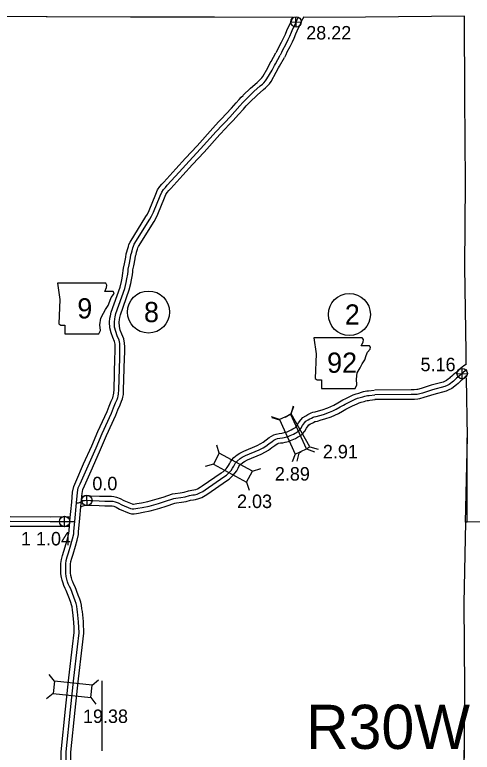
# Model space of a CAD drawing. Extents: x 31699 to 244310, y -8841 to 11474.
# Drawn here: x 102114 to 103072, y 4850 to 6393 of the extents above; entities that cross this region are included whole.
import ezdxf

# ---------------------------------------------------------------- set-up
doc = ezdxf.new("R2010")
doc.units = 0
for name, color, linetype in [('B_Logo', 7, 'Continuous'), ('Default', 7, 'Continuous'), ('G-ANNO-TEXT', 7, 'Continuous'), ('Level 21', 7, 'Continuous'), ('R_Border', 7, 'Continuous'), ('R_Border Notes', 7, 'Continuous'), ('R_Logo', 7, 'Continuous'), ('R_XS_EARTHWORK_STAGE1', 7, 'Continuous'), ('R_XS_EARTHWORK_STAGE2', 7, 'Continuous'), ('S_WALL', 7, 'Continuous'), ('S_WALL_ANNOT', 7, 'Continuous')]:
    doc.layers.add(name, color=color, linetype=linetype)

msp = doc.modelspace()

# ---------------------------------------------------------------- linework, layer by layer
at = {"layer": 'B_Logo'}
for points in [[(102707.1, 6388.4), (102704.5, 6382.7), (102701.3, 6375.7), (102698.4, 6369.4), (102695.1, 6363.2), (102692.1, 6356), (102689, 6347.8), (102685.5, 6340.5), (102680.4, 6330.5), (102674.5, 6319), (102672.2, 6313.9), (102669.4, 6308.7)], [(102598.9, 6217.5), (102614.3, 6232.3), (102627.6, 6244.3), (102632.2, 6248), (102635.5, 6251), (102639, 6254.9), (102641.7, 6259), (102652.3, 6277.6), (102657.5, 6287.3), (102659.5, 6290.5), (102669.4, 6308.7)], [(102244.7, 5393.2), (102246.7, 5402.9), (102250.6, 5411.5), (102267, 5449.3), (102284.1, 5487.1), (102296.5, 5516.9), (102315.9, 5559.2), (102320.5, 5570.3), (102324.9, 5580.8), (102328, 5587.9), (102329.5, 5592.3), (102330.3, 5595.3), (102331.2, 5599.8), (102331.6, 5608.6), (102333.5, 5674.7), (102334, 5686.5), (102334, 5698.2), (102333.7, 5705.2), (102332.3, 5712.2), (102328.4, 5721.4), (102325.2, 5730.4), (102322.7, 5739.5), (102322.3, 5749.9), (102322.9, 5757), (102323.7, 5761.4), (102325.3, 5767.9), (102343.8, 5820.2), (102347.2, 5832.7), (102348.4, 5840.3), (102350.1, 5850.7), (102350.8, 5856.6), (102351.3, 5860.9), (102353.4, 5869.7), (102355.8, 5884.3), (102357, 5890.7), (102357.9, 5894.4), (102359.3, 5899), (102361.2, 5905.5), (102362.2, 5908.9), (102364, 5912.8), (102396.8, 5965.7), (102400.1, 5971.4), (102404.3, 5979.8), (102418.1, 6014.1), (102421.5, 6022), (102425.2, 6027.6), (102429, 6031.9), (102433.1, 6036.6), (102458, 6064.1), (102478.6, 6086.5), (102502.6, 6112.3), (102535.7, 6149.1), (102547.9, 6162.2), (102554, 6168.8), (102563.7, 6178.8), (102574.8, 6191.1), (102584.9, 6202.3), (102591, 6209.4), (102595.2, 6213.7), (102598.9, 6217.5)], [(103060.3, 5650.4), (103060.1, 5650.3), (103053.2, 5645.2), (103050.4, 5642.8), (103045.6, 5638.1), (103041.5, 5634.9), (103038.7, 5632.5), (103035.2, 5629.2), (103032.1, 5626.7)], [(103032.1, 5626.7), (103023.6, 5619.7), (103021.8, 5618.9), (103019.4, 5617.7), (103013.9, 5615.2), (102988.3, 5608.4), (102967.6, 5601.5), (102959.2, 5599.3), (102956.5, 5598.8), (102950.2, 5598.4), (102943.6, 5598.3), (102867.3, 5597.8)], [(102512, 5399), (102551.3, 5426.1), (102556.8, 5429.4), (102560.8, 5433.1), (102564.1, 5436.7), (102566.5, 5439.7), (102569.9, 5444.4), (102572.3, 5448.8), (102574.3, 5452.8), (102576.2, 5455.7), (102579.5, 5459.3), (102585.4, 5464.5), (102589.6, 5467.2), (102597.1, 5470.8), (102625.2, 5482.9), (102633.6, 5487.1), (102639.2, 5490.5), (102646, 5495.6), (102652.4, 5500.3), (102656, 5502.7), (102660.3, 5505.1), (102663.5, 5506.1), (102668.5, 5507.2), (102674, 5507.6), (102677.8, 5508.3), (102683.5, 5509.9), (102687.4, 5511.3), (102690.6, 5512.6), (102697.2, 5515.6), (102700.9, 5517.8), (102703.4, 5519.1), (102707.4, 5521.6), (102709.3, 5523.2), (102712.7, 5527.2), (102716.1, 5533.6), (102720.2, 5539.3), (102723.2, 5542.5), (102728, 5545.7), (102731.7, 5547.7), (102734.8, 5549.1), (102738.3, 5550.9), (102740.4, 5551.7), (102745, 5552.5), (102752.3, 5554.9), (102760.1, 5556.9), (102772.6, 5561.5), (102779.8, 5564.5), (102786.7, 5567.7), (102795.1, 5572.5), (102801.8, 5576.5), (102805.4, 5578.4), (102811.2, 5581.3), (102816.9, 5584.1), (102826.7, 5588.5), (102831.6, 5590.7), (102836.6, 5592), (102842.4, 5593.6), (102846.5, 5594.8), (102849.8, 5595.5), (102852.6, 5596.1), (102855.5, 5596.6), (102867.3, 5597.8)], [(102221.2, 4806.1), (102221, 4850.6), (102230.1, 4938.6), (102237.1, 5004.6), (102244.8, 5070.1), (102248.2, 5099.9), (102248.2, 5102.9), (102248, 5108), (102247.9, 5111), (102247.3, 5122.9), (102245.2, 5143.4), (102244.4, 5148.9), (102243.5, 5155.8), (102242.2, 5161.1), (102240.4, 5166.6), (102237.3, 5174.7), (102230.8, 5192), (102228.4, 5196.9), (102225.8, 5202.6), (102224.3, 5206.4), (102222.8, 5212.4), (102221.5, 5217.7), (102220.4, 5224.3), (102220.3, 5229.9), (102220.3, 5237.4), (102220.4, 5244.2), (102221.3, 5251.2), (102223.3, 5258.6), (102226.2, 5267.5), (102231, 5284), (102234.6, 5296.4), (102237.1, 5307.1), (102237.5, 5312.5), (102239.2, 5332.9), (102242.8, 5372.1), (102244.7, 5393.2)], [(102242.8, 5372.1), (102247.4, 5372.1), (102249.2, 5372.8), (102250.5, 5373.5), (102252.7, 5374.6), (102255.1, 5375.6), (102256.4, 5376.1), (102260, 5376.8), (102263.1, 5377.1), (102272.1, 5376.7), (102290.6, 5376), (102302.3, 5375.5), (102311.8, 5375.6), (102315.4, 5375.6), (102319.3, 5375.2), (102323.8, 5374.2), (102330.4, 5371.6), (102337.6, 5367.6), (102356.2, 5359.9), (102359.7, 5359.1), (102363.2, 5359), (102367.1, 5359.6), (102371.3, 5360.3), (102380.7, 5362), (102394.8, 5364.9), (102404.9, 5367.6), (102414.4, 5370.4), (102427.4, 5374.5), (102446.5, 5380.9), (102450.7, 5381.5), (102461.5, 5383.1), (102470.5, 5384.6), (102479.6, 5387.1), (102486.3, 5388.3), (102490.3, 5388.8), (102495.8, 5390.2), (102500.9, 5392.4), (102507.3, 5395.7), (102512, 5399)], [(102104.1, 5333.1), (102187.9, 5332.8), (102239.2, 5332.9)]]:
    msp.add_lwpolyline(points, dxfattribs=at)
at = {"layer": 'Default'}
msp.add_line((102296.2, 4999.1), (102296.2, 4852.8), dxfattribs=at)
at = {"layer": 'G-ANNO-TEXT'}
for points in [[(102202.8, 5831.3), (102207.9, 5797.4), (102205.6, 5746.1), (102210.2, 5743.3), (102218.6, 5743.3), (102218.6, 5725.3), (102289.7, 5725.3), (102293.1, 5732.6), (102291.9, 5744.4), (102293.6, 5758), (102299.8, 5768.7), (102303.8, 5776.6), (102309.4, 5785), (102312.8, 5794), (102315.6, 5801.4), (102320.7, 5807.6), (102321.8, 5811.5), (102319.6, 5814.4), (102302.1, 5814.4), (102306, 5822.2), (102306.6, 5827.3), (102304.3, 5831.2)], [(102739.8, 5717.2), (102744.9, 5683.4), (102742.7, 5632.1), (102747.2, 5629.3), (102755.6, 5629.3), (102755.6, 5611.2), (102826.7, 5611.2), (102830.1, 5618.5), (102828.9, 5630.4), (102830.6, 5643.9), (102836.8, 5654.6), (102840.8, 5662.5), (102846.4, 5671), (102849.8, 5680), (102852.6, 5687.3), (102857.7, 5693.6), (102858.8, 5697.5), (102856.6, 5700.3), (102839.1, 5700.3), (102843, 5708.2), (102843.6, 5713.3), (102841.3, 5717.2)]]:
    msp.add_lwpolyline(points, close=True, dxfattribs=at)
at = {"layer": 'Level 21'}
for p, q in [((102691.7, 6378), (102713.4, 6378.5)), ((102702.8, 6367.4), (102702.3, 6389.1)), ((103050.8, 5631.4), (103050.3, 5653.1)), ((103039.7, 5642), (103061.4, 5642.5)), ((102264.9, 5366.2), (102264.4, 5387.9)), ((102253.8, 5376.8), (102275.5, 5377.3)), ((102218.1, 5321.9), (102217.6, 5343.6)), ((102207, 5332.5), (102228.7, 5333))]:
    msp.add_line(p, q, dxfattribs=at)
for centre in [(102702.6, 6378.2), (103050.5, 5642.2), (102264.6, 5377), (102217.9, 5332.8)]:
    msp.add_circle(centre, 10.9, dxfattribs=at)
at = {"layer": 'R_Border Notes'}
for centre in [(102393.7, 5771.1), (102814.3, 5766)]:
    msp.add_circle(centre, 44, dxfattribs=at)
at = {"layer": 'R_Logo'}
for points in [[(102696.2, 6387.4), (102531.9, 6387.9), (102358.4, 6388.1), (102355.8, 6388.5), (102181.6, 6388.9), (102179.6, 6388.9), (102005.1, 6390.4), (102003.4, 6390.4), (101829.9, 6391.6), (101826.9, 6391.9), (101654.1, 6392.9), (101649.9, 6393.1), (101606.2, 6393.3)], [(103059.1, 5662.1), (103058.7, 5687.5), (103056.2, 5864.8), (103057.3, 6042.5), (103056.4, 6220.8), (103055.4, 6390), (102847.8, 6388.1)], [(102847.8, 6388.1), (102719, 6387.8)], [(103057.5, 5331.4), (103061.8, 5510.2), (103059.6, 5632.5)], [(103061, 5331.5), (103061, 5507.5)], [(103766.5, 5336.1), (103736.6, 5336.3), (103686.7, 5336.6), (103590, 5337.3), (103413.2, 5334.7), (103411.6, 5334.8), (103233, 5334.1), (103230.4, 5334.1), (103061, 5331.5), (103057.5, 5331.4), (103053.7, 5162.1), (103055.2, 4984.7), (103054.3, 4811.7)], [(103167.5, 5333.1), (103061, 5331.5), (103057.5, 5331.4), (103053.7, 5162.1), (103055.2, 4984.7), (103054.2, 4787.8)]]:
    msp.add_lwpolyline(points, dxfattribs=at)
at = {"layer": 'R_XS_EARTHWORK_STAGE1'}
for p, q in [((102692, 5556.8), (102698.2, 5573.3)), ((102692.5, 5557.9), (102697.1, 5574.8)), ((102692.5, 5557.9), (102680, 5550.7)), ((102731.7, 5489.1), (102692.5, 5557.9)), ((102668, 5545.9), (102651.5, 5552.1)), ((102668.7, 5545), (102652.6, 5549.4)), ((102542, 5476), (102536.9, 5492.8)), ((102724.8, 5484.7), (102741.2, 5478.5)), ((102725.3, 5485.4), (102731.7, 5489.1)), ((102731.7, 5489.1), (102748.7, 5484.4)), ((102700.7, 5473.8), (102694.5, 5457.3)), ((102708.8, 5476), (102704.2, 5459)), ((102708.5, 5476.5), (102708.8, 5476)), ((102708.8, 5476), (102713.2, 5478.5)), ((102529.5, 5452.7), (102512.6, 5447.7)), ((102611.7, 5438.4), (102628.6, 5443.5)), ((102599.2, 5415.2), (102604.3, 5398.3)), ((102196.7, 4998.8), (102185.6, 5012.5)), ((102275.4, 4990.4), (102289.1, 5001.5)), ((102193.9, 4972.6), (102180.2, 4961.5)), ((102272.6, 4964.2), (102283.7, 4950.5))]:
    msp.add_line(p, q, dxfattribs=at)
for points in [[(102668, 5545.9), (102700.7, 5473.8), (102724.8, 5484.7), (102692, 5556.8)], [(102529.5, 5452.7), (102599.2, 5415.2), (102611.7, 5438.4), (102542, 5476)], [(102275.4, 4990.4), (102196.7, 4998.8), (102193.9, 4972.6), (102272.6, 4964.2)]]:
    msp.add_lwpolyline(points, close=True, dxfattribs=at)
at = {"layer": 'R_XS_EARTHWORK_STAGE2'}
for points in [[(102696.2, 6388.5), (102695.5, 6386.9), (102692.2, 6379.9), (102689.5, 6373.8), (102686, 6367.5), (102682.8, 6359.7), (102679.8, 6351.7), (102676.5, 6344.9), (102671.5, 6335.1), (102665.5, 6323.3), (102663.3, 6318.4), (102660.6, 6313.4)], [(102719, 6388.8), (102716.1, 6384), (102713.6, 6378.5), (102710.4, 6371.5), (102707.4, 6365), (102704.1, 6358.9), (102701.4, 6352.3), (102698.2, 6343.8), (102694.4, 6336), (102689.3, 6326), (102683.5, 6314.6), (102681.2, 6309.5), (102678.2, 6304)], [(102592, 6224.8), (102607.5, 6239.7), (102621.1, 6251.8), (102625.6, 6255.6), (102628.4, 6258.1), (102631.1, 6261.1), (102633.2, 6264.2), (102643.5, 6282.4), (102648.8, 6292.3), (102650.8, 6295.5), (102660.6, 6313.5)], [(102605.8, 6210.3), (102621.1, 6225), (102634.2, 6236.7), (102638.7, 6240.4), (102642.5, 6243.9), (102646.9, 6248.7), (102650.3, 6253.7), (102661, 6272.8), (102666.1, 6282.2), (102668.1, 6285.4), (102678.2, 6303.9)], [(102234.7, 5394.4), (102237.1, 5406), (102241.4, 5415.6), (102257.8, 5453.3), (102274.9, 5491.1), (102287.4, 5520.9), (102306.8, 5563.2), (102311.3, 5574.1), (102315.7, 5584.7), (102318.7, 5591.5), (102319.9, 5595.2), (102320.6, 5597.6), (102321.2, 5601), (102321.6, 5609), (102323.5, 5675.1), (102324, 5686.7), (102324, 5698), (102323.8, 5704), (102322.7, 5709.2), (102319, 5717.8), (102315.6, 5727.4), (102312.8, 5738), (102312.2, 5750.2), (102313, 5758.4), (102314, 5763.5), (102315.7, 5770.7), (102334.2, 5823.2), (102337.4, 5834.9), (102338.6, 5841.9), (102340.1, 5852.1), (102340.9, 5857.8), (102341.4, 5862.6), (102343.5, 5871.7), (102345.9, 5886), (102347.2, 5892.8), (102348.3, 5897), (102349.7, 5901.8), (102351.6, 5908.3), (102352.8, 5912.5), (102355.3, 5917.6), (102388.2, 5970.8), (102391.3, 5976.1), (102395.2, 5983.9), (102408.9, 6017.9), (102412.6, 6026.7), (102417.2, 6033.8), (102421.6, 6038.5), (102425.6, 6043.2), (102450.7, 6070.8), (102471.2, 6093.3), (102495.3, 6119.1), (102528.3, 6155.8), (102540.5, 6169), (102546.7, 6175.7), (102556.4, 6185.6), (102567.4, 6197.8), (102577.4, 6208.9), (102583.6, 6216.1), (102588, 6220.6), (102591.7, 6224.5)], [(102254.5, 5391.2), (102256.2, 5399.8), (102259.7, 5407.5), (102276.1, 5445.2), (102293.2, 5483.1), (102305.7, 5512.9), (102325.1, 5555.2), (102329.7, 5566.4), (102334.1, 5576.9), (102337.3, 5584.3), (102339, 5589.3), (102340.1, 5593.1), (102341.1, 5598.7), (102341.6, 5608.2), (102343.5, 5674.3), (102344, 5686.3), (102344, 5698.4), (102343.7, 5706.3), (102341.9, 5715.2), (102337.7, 5725.1), (102334.7, 5733.4), (102332.7, 5741), (102332.3, 5749.7), (102332.9, 5755.6), (102333.5, 5759.4), (102334.9, 5765.1), (102353.4, 5817.3), (102356.9, 5830.6), (102358.3, 5838.7), (102360, 5849.3), (102360.7, 5855.4), (102361.1, 5859.2), (102363.2, 5867.8), (102365.6, 5882.5), (102366.8, 5888.5), (102367.6, 5891.8), (102368.9, 5896.2), (102370.8, 5902.7), (102371.5, 5905.3), (102372.8, 5908), (102405.4, 5960.6), (102408.9, 5966.6), (102413.4, 5975.7), (102427.4, 6010.3), (102430.3, 6017.3), (102433.1, 6021.5), (102436.5, 6025.2), (102440.6, 6029.9), (102465.4, 6057.3), (102485.9, 6079.7), (102510, 6105.6), (102543.1, 6142.3), (102555.2, 6155.4), (102561.2, 6161.9), (102571, 6171.9), (102582.3, 6184.4), (102592.4, 6195.7), (102598.4, 6202.6), (102602.4, 6206.8), (102606.1, 6210.6)], [(103059.3, 5662.1), (103054.2, 5658.4), (103047, 5653), (103043.6, 5650.2), (103039, 5645.6), (103035.2, 5642.7), (103032, 5640), (103028.6, 5636.7), (103025.7, 5634.4)], [(103025.8, 5634.4), (103018.2, 5628.2), (103017.5, 5627.9), (103015.2, 5626.7), (103010.5, 5624.6), (102985.4, 5618), (102964.7, 5611.1), (102956.9, 5609), (102955.3, 5608.7), (102949.8, 5608.4), (102943.5, 5608.3), (102867.3, 5607.8)], [(103059.5, 5637.4), (103059.4, 5637.3), (103057.1, 5635.4), (103052.1, 5630.5), (103047.8, 5627.2), (103045.4, 5625.1), (103041.8, 5621.7), (103038.5, 5619)], [(103038.4, 5618.9), (103029, 5611.2), (103026.2, 5609.9), (103023.7, 5608.7), (103017.3, 5605.7), (102991.1, 5598.8), (102970.4, 5592), (102961.4, 5589.5), (102957.7, 5588.8), (102950.6, 5588.4), (102943.8, 5588.3), (102867.4, 5587.8)], [(102506.3, 5407.3), (102545.9, 5434.6), (102550.8, 5437.5), (102553.7, 5440.1), (102556.5, 5443.2), (102558.6, 5445.8), (102561.4, 5449.7), (102563.5, 5453.5), (102565.6, 5457.7), (102568.2, 5461.7), (102572.5, 5466.5), (102579.4, 5472.5), (102584.7, 5476), (102593, 5479.9), (102620.9, 5491.9), (102628.7, 5495.9), (102633.6, 5498.8), (102640, 5503.6), (102646.7, 5508.6), (102650.9, 5511.3), (102656.2, 5514.2), (102660.8, 5515.8), (102667.1, 5517.1), (102672.7, 5517.5), (102675.5, 5518.1), (102680.5, 5519.4), (102683.8, 5520.6), (102686.5, 5521.8), (102692.6, 5524.6), (102696.1, 5526.5), (102698.5, 5527.8), (102701.5, 5529.7), (102702.2, 5530.3), (102704.3, 5532.8), (102707.6, 5538.9), (102712.5, 5545.6), (102716.6, 5550.2), (102722.9, 5554.2), (102727.1, 5556.6), (102730.4, 5558.2), (102734.3, 5560.1), (102737.7, 5561.3), (102742.6, 5562.3), (102749.5, 5564.5), (102757.1, 5566.4), (102768.9, 5570.8), (102775.8, 5573.6), (102782.1, 5576.5), (102790, 5581.2), (102796.9, 5585.2), (102800.9, 5587.3), (102806.8, 5590.2), (102812.7, 5593.1), (102822.6, 5597.6), (102828.2, 5600.1), (102834, 5601.6), (102839.6, 5603.2), (102844, 5604.5), (102847.7, 5605.3), (102850.6, 5605.9), (102854.1, 5606.5), (102866.3, 5607.7)], [(102517.6, 5390.8), (102556.7, 5417.7), (102562.9, 5421.4), (102567.8, 5426), (102571.7, 5430.1), (102574.5, 5433.6), (102578.4, 5439), (102581.2, 5444.2), (102583.1, 5447.8), (102584.1, 5449.6), (102586.5, 5452.2), (102591.5, 5456.5), (102594.5, 5458.4), (102601.3, 5461.7), (102629.4, 5473.8), (102638.5, 5478.4), (102644.8, 5482.2), (102651.9, 5487.6), (102658, 5492.1), (102661.2, 5494.1), (102664.4, 5495.9), (102666.1, 5496.5), (102669.9, 5497.3), (102675.3, 5497.7), (102680.1, 5498.6), (102686.5, 5500.4), (102691, 5502), (102694.6, 5503.5), (102701.7, 5506.7), (102705.7, 5509), (102708.4, 5510.4), (102713.3, 5513.5), (102716.4, 5516.1), (102721, 5521.6), (102724.6, 5528.3), (102728, 5532.9), (102729.7, 5534.8), (102733.2, 5537.1), (102736.2, 5538.8), (102739.1, 5540.1), (102742.3, 5541.7), (102743.1, 5542), (102747.5, 5542.8), (102755.1, 5545.3), (102763.1, 5547.3), (102776.2, 5552.1), (102783.8, 5555.3), (102791.4, 5558.8), (102800.1, 5563.9), (102806.6, 5567.7), (102810, 5569.5), (102815.6, 5572.3), (102821.2, 5575), (102830.9, 5579.3), (102834.9, 5581.2), (102839.2, 5582.3), (102845.2, 5584), (102849, 5585.1), (102851.8, 5585.7), (102854.5, 5586.3), (102856.9, 5586.7), (102868.3, 5587.8)], [(102254.4, 5385.9), (102258.6, 5386.7), (102262.8, 5387.1), (102272.5, 5386.7), (102291, 5386), (102302.4, 5385.5), (102311.8, 5385.6), (102315.9, 5385.6), (102320.8, 5385.1), (102326.8, 5383.8), (102334.6, 5380.6), (102341.9, 5376.7), (102359.3, 5369.5), (102361, 5369), (102362.5, 5369), (102365.5, 5369.5), (102369.5, 5370.2), (102378.8, 5371.8), (102392.5, 5374.6), (102402.2, 5377.2), (102411.5, 5380), (102424.3, 5384), (102444.1, 5390.6), (102449.2, 5391.4), (102459.9, 5393), (102468.4, 5394.4), (102477.4, 5396.9), (102484.7, 5398.2), (102488.5, 5398.7), (102492.6, 5399.7), (102496.6, 5401.4), (102502.1, 5404.3), (102506.2, 5407.2)], [(102211.2, 4806), (102211, 4851), (102220.2, 4939.7), (102227.2, 5005.7), (102234.8, 5071.2), (102238.2, 5100.6), (102238.2, 5102.8), (102238, 5107.6), (102237.9, 5110.5), (102237.3, 5122.2), (102235.3, 5142.1), (102234.5, 5147.5), (102233.6, 5153.9), (102232.6, 5158.4), (102231, 5163.2), (102228, 5171.2), (102221.6, 5188), (102219.3, 5192.7), (102216.5, 5198.7), (102214.8, 5203.4), (102213.1, 5210), (102211.7, 5215.7), (102210.4, 5223.4), (102210.3, 5229.8), (102210.3, 5237.5), (102210.4, 5244.9), (102211.4, 5253.2), (102213.7, 5261.4), (102216.6, 5270.5), (102221.5, 5286.8), (102225, 5298.9), (102227.1, 5308.5), (102227.5, 5313.3), (102229.2, 5333.8), (102232.9, 5373), (102234.7, 5394.2)], [(102231.2, 4806.1), (102231, 4850.1), (102240.1, 4937.6), (102247.1, 5003.5), (102254.7, 5068.9), (102258.2, 5099.3), (102258.2, 5103), (102258, 5108.5), (102257.8, 5111.5), (102257.3, 5123.6), (102255.2, 5144.6), (102254.3, 5150.3), (102253.3, 5157.6), (102251.8, 5163.8), (102249.8, 5169.9), (102246.7, 5178.3), (102240, 5195.9), (102237.4, 5201.2), (102235, 5206.4), (102233.9, 5209.5), (102232.4, 5214.9), (102231.3, 5219.7), (102230.4, 5225.2), (102230.3, 5230), (102230.3, 5237.4), (102230.4, 5243.5), (102231.1, 5249.2), (102232.9, 5255.7), (102235.7, 5264.6), (102240.6, 5281.2), (102244.3, 5293.9), (102247, 5305.6), (102247.4, 5311.7), (102249.1, 5332), (102252.8, 5371.2), (102254.6, 5392.3)], [(102252.4, 5363.3), (102253.5, 5363.8), (102255.1, 5364.6), (102256.8, 5365.5), (102258.7, 5366.3), (102259.1, 5366.4), (102261.5, 5366.9), (102263.4, 5367.1), (102271.7, 5366.7), (102290.2, 5366), (102302.1, 5365.5), (102311.8, 5365.6), (102314.9, 5365.6), (102317.7, 5365.3), (102320.8, 5364.6), (102326.1, 5362.5), (102333.3, 5358.6), (102353, 5350.4), (102358.4, 5349.1), (102363.9, 5349), (102368.7, 5349.7), (102373, 5350.5), (102382.6, 5352.2), (102397.1, 5355.2), (102407.6, 5358), (102417.3, 5360.8), (102430.5, 5365), (102448.8, 5371.1), (102452.1, 5371.6), (102463, 5373.2), (102472.7, 5374.8), (102481.8, 5377.4), (102487.8, 5378.4), (102492.1, 5379), (102498.9, 5380.6), (102505.1, 5383.3), (102512.5, 5387.1), (102517.7, 5390.9)], [(102104.1, 5343.1), (102187.9, 5342.8), (102229.6, 5342.9)], [(102104.1, 5323.1), (102187.9, 5322.8), (102227.8, 5322.9)]]:
    msp.add_lwpolyline(points, dxfattribs=at)

# ---------------------------------------------------------------- texts
at = {"layer": 'G-ANNO-TEXT'}
for s, height, p in [('9', 42.2, (102244.6, 5757.7)), ('92', 42.24, (102767.7, 5644))]:
    msp.add_text(s, height=height, dxfattribs=at).set_placement(p)
at = {"layer": 'R_Border'}
msp.add_text('R30W', height=92.4, dxfattribs=at).set_placement((102723.5, 4856.8))
at = {"layer": 'R_Border Notes'}
for s, p in [('8', (102384.2, 5750)), ('2', (102804.8, 5744.9))]:
    msp.add_text(s, height=42.2, dxfattribs=at).set_placement(p)
at = {"layer": 'S_WALL'}
for s, p in [('2.91', (102758.8, 5464.9)), ('2.89', (102658.3, 5418.4)), ('2.03', (102579.1, 5360.9)), ('19.38', (102256.5, 4911.1))]:
    msp.add_text(s, height=28.16, dxfattribs=at).set_placement(p)
at = {"layer": 'S_WALL_ANNOT'}
for s, p in [('28.22', (102724, 6341.5)), ('5.16', (102963.4, 5647.3)), ('0.0', (102276.1, 5398.1)), ('1 1.04', (102126.7, 5282.7))]:
    msp.add_text(s, height=28.16, dxfattribs=at).set_placement(p)

doc.saveas('drawing.dxf')
